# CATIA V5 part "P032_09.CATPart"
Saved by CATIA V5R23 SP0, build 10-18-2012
Part number: 05-LICP-T02-E-S03-P032_09
Bounding box of the stored display mesh (mm): x 2.6 to 18.4, y -14.998 to 14.998, z -14.998 to 14.998
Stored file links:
  C:\wamp\www\COURS\CONCEPTION GMP1\TITRE 02-SEMESTRE 2\03-TP7-PRESSE MECANIQUE\eleve\P032_09.CATPart
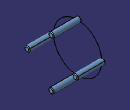
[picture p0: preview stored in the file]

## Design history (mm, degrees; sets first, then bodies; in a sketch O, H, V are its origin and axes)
Body1 (main body)
  Solid1: solid without history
